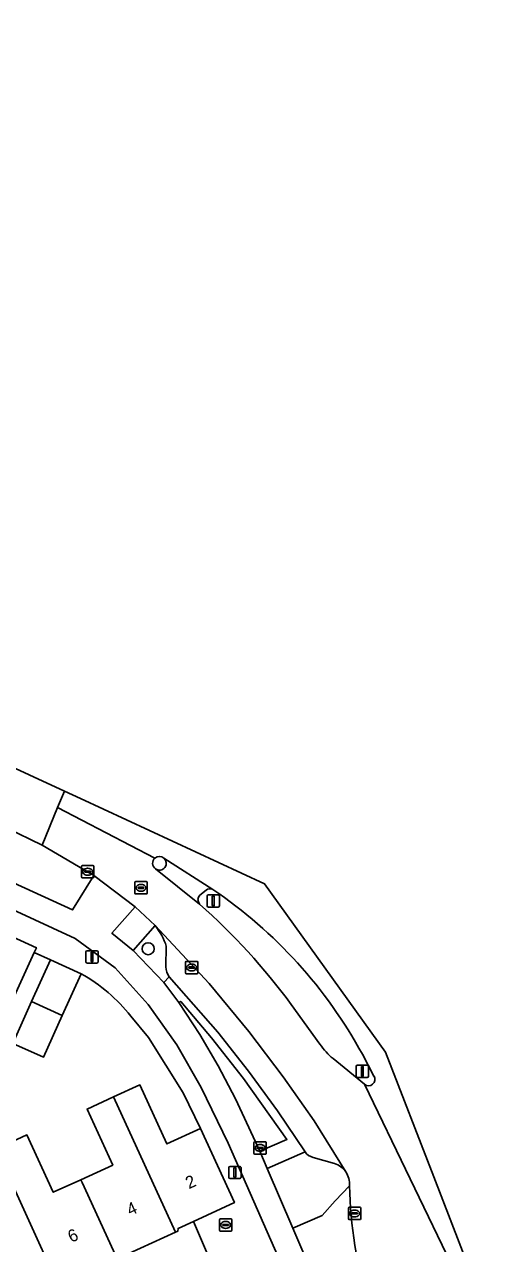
# Model space of a CAD drawing. Extents: x 161838 to 162344, y 381620 to 382160.
# Drawn here: x 162267.7 to 162305.1, y 381756.3 to 381855.3 of the extents above; entities that cross this region are included whole.
import ezdxf

# ---------------------------------------------------------------- set-up
doc = ezdxf.new("R2010")
doc.units = 0
for name, color, linetype in [('IMGEO_Berm_groen', 7, 'Continuous'), ('IMGEO_Boom', 7, 'Continuous'), ('IMGEO_Brandkraan', 7, 'Continuous'), ('IMGEO_Erf', 7, 'Continuous'), ('IMGEO_Kolk', 7, 'Continuous'), ('IMGEO_Lichtmast', 7, 'Continuous'), ('IMGEO_Muur', 7, 'Continuous'), ('IMGEO_Pand', 7, 'Continuous'), ('IMGEO_Pand_nummerreeks', 7, 'Continuous'), ('IMGEO_Parkeervlak_open', 7, 'Continuous'), ('IMGEO_Rijbaan_lokaal_gesloten', 7, 'Continuous'), ('IMGEO_Rioolput', 7, 'Continuous'), ('IMGEO_Verkeerseiland_groen', 7, 'Continuous'), ('IMGEO_Verkeerseiland_open', 7, 'Continuous'), ('IMGEO_Voetpad_gesloten', 7, 'Continuous'), ('IMGEO_Voetpad_open', 7, 'Continuous')]:
    doc.layers.add(name, color=color, linetype=linetype)

msp = doc.modelspace()

# ---------------------------------------------------------------- linework, layer by layer
at = {"layer": 'IMGEO_Berm_groen'}
for points in [[(162278.32, 381782.137), (162276.556, 381780.102), (162279.031, 381777.525), (162279.473, 381777.981)], [(162279.197, 381778.777), (162279.235, 381780.454)], [(162290.497, 381763.771), (162287.421, 381762.394), (162289.504, 381757.563), (162291.89, 381758.597), (162292.955, 381759.774), (162294.11, 381761.009)], [(162292.898, 381762.818), (162291.154, 381763.302)]]:
    msp.add_lwpolyline(points, dxfattribs=at)
msp.add_lwpolyline([(162282.909, 381773.006), (162280.411, 381775.98), (162280.238, 381775.879), (162281.96, 381773.297), (162283.451, 381770.742), (162284.848, 381768.06), (162286.825, 381763.803), (162289.022, 381764.764), (162285.512, 381769.728)], close=True, dxfattribs=at)
for centre, radius, start, end in [((162274.478, 381778.958), 4.986, 17.45711, 39.60627), ((162280.501, 381778.783), 1.304, 180.28188, 217.96443), ((162291.365, 381764.292), 1.012, 210.98439, 257.97326), ((162292.325, 381761.122), 1.79, 34.08019, 71.33847), ((162292.331, 381761.126), 1.783, 356.22586, 34.05836)]:
    msp.add_arc(centre, radius, start, end, dxfattribs=at)
at = {"layer": 'IMGEO_Boom'}
msp.add_circle((162277.76, 381780.26), 0.489, dxfattribs=at)
at = {"layer": 'IMGEO_Brandkraan'}
for p, q in [((162283.553, 381757.394), (162283.553, 381758.246)), ((162283.628, 381758.32), (162284.48, 381758.32)), ((162283.812, 381757.814), (162283.812, 381757.826)), ((162284.25, 381757.777), (162283.852, 381757.777)), ((162283.855, 381757.863), (162284.253, 381757.863)), ((162284.041, 381758.1), (162284.066, 381758.1)), ((162284.296, 381757.826), (162284.296, 381757.814)), ((162284.554, 381758.246), (162284.554, 381757.394)), ((162284.48, 381757.32), (162283.628, 381757.32)), ((162284.064, 381757.54), (162284.039, 381757.54))]:
    msp.add_line(p, q, dxfattribs=at)
for points in [[(162283.553, 381757.394), (162283.553, 381758.246)], [(162283.628, 381758.32), (162284.48, 381758.32)], [(162284.554, 381758.246), (162284.554, 381757.394)], [(162284.48, 381757.32), (162283.628, 381757.32)]]:
    msp.add_lwpolyline(points, dxfattribs=at)
for centre, radius, start, end in [((162283.63, 381758.244), 0.0765, 91.55205, 178.44795), ((162283.63, 381758.244), 0.0765, 91.55205, 178.44795), ((162283.852, 381757.823), 0.0403, 85.87752, 175.75265), ((162283.849, 381757.813), 0.0366, 178.93798, 274.71019), ((162284.253, 381757.82), 0.043, 264.86636, 352.45326), ((162284.257, 381757.825), 0.0386, 1.73085, 96.63898), ((162284.478, 381758.244), 0.0765, 1.55205, 88.44795), ((162284.478, 381758.244), 0.0765, 1.55205, 88.44795), ((162283.63, 381757.396), 0.0765, 181.55205, 268.44795), ((162283.63, 381757.396), 0.0765, 181.55205, 268.44795), ((162284.478, 381757.396), 0.0765, 271.55205, 358.44795), ((162284.478, 381757.396), 0.0765, 271.55205, 358.44795)]:
    msp.add_arc(centre, radius, start, end, dxfattribs=at)
for centre, major_axis, ratio, start_param, end_param in [((162284.04, 381757.82), (-0.387, 0.002), 0.722429, 4.712389, 7.853982), ((162284.065, 381757.82), (-0.39, 0.002), 0.717154, 1.570796, 4.712389)]:
    msp.add_ellipse(centre, major_axis=major_axis, ratio=ratio, start_param=start_param, end_param=end_param, dxfattribs=at)
at = {"layer": 'IMGEO_Erf'}
for points in [[(162272.328, 381778.227), (162270.79, 381774.833), (162269.254, 381771.442), (162266.766, 381772.568), (162268.303, 381775.962), (162269.84, 381779.353), (162268.511, 381779.959), (162266.621, 381775.786)], [(162277.781, 381773.055), (162276.358, 381774.78)], [(162260.558, 381756.131), (162262.824, 381757.166), (162265.353, 381758.321), (162263.22, 381762.989), (162265.401, 381763.985), (162267.923, 381765.137), (162270.053, 381760.473), (162272.292, 381761.495), (162274.881, 381762.678), (162272.802, 381767.23), (162274.96, 381768.215), (162277.096, 381769.191), (162279.286, 381764.396), (162282.012, 381765.641), (162280.601, 381768.553), (162277.781, 381773.055)]]:
    msp.add_lwpolyline(points, dxfattribs=at)
msp.add_arc((162265.362, 381766.004), 14.069, 38.59496, 60.32198, dxfattribs=at)
at = {"layer": 'IMGEO_Kolk'}
for p, q in [((162272.355, 381786.085), (162272.355, 381786.937)), ((162272.43, 381787.011), (162273.282, 381787.011)), ((162272.614, 381786.505), (162272.614, 381786.517)), ((162273.052, 381786.468), (162272.654, 381786.468)), ((162272.657, 381786.554), (162273.055, 381786.554)), ((162272.843, 381786.791), (162272.868, 381786.791)), ((162273.098, 381786.517), (162273.098, 381786.505)), ((162273.356, 381786.937), (162273.356, 381786.085)), ((162273.282, 381786.011), (162272.43, 381786.011)), ((162272.866, 381786.231), (162272.841, 381786.231)), ((162280.79, 381778.304), (162280.79, 381779.156)), ((162280.865, 381779.23), (162281.717, 381779.23)), ((162281.049, 381778.724), (162281.049, 381778.736)), ((162281.487, 381778.687), (162281.089, 381778.687)), ((162281.092, 381778.773), (162281.49, 381778.773)), ((162281.301, 381778.45), (162281.276, 381778.45)), ((162281.278, 381779.01), (162281.303, 381779.01)), ((162281.533, 381778.736), (162281.533, 381778.724)), ((162281.791, 381779.156), (162281.791, 381778.304)), ((162281.717, 381778.23), (162280.865, 381778.23)), ((162286.351, 381763.646), (162286.351, 381764.498)), ((162286.426, 381764.572), (162287.278, 381764.572)), ((162287.352, 381764.498), (162287.352, 381763.646)), ((162287.278, 381763.572), (162286.426, 381763.572)), ((162286.61, 381764.066), (162286.61, 381764.078)), ((162287.048, 381764.029), (162286.65, 381764.029)), ((162286.653, 381764.115), (162287.051, 381764.115)), ((162286.862, 381763.792), (162286.837, 381763.792)), ((162286.839, 381764.352), (162286.864, 381764.352)), ((162287.094, 381764.078), (162287.094, 381764.066))]:
    msp.add_line(p, q, dxfattribs=at)
for points in [[(162272.355, 381786.085), (162272.355, 381786.937)], [(162272.43, 381787.011), (162273.282, 381787.011)], [(162273.356, 381786.937), (162273.356, 381786.085)], [(162273.282, 381786.011), (162272.43, 381786.011)], [(162280.79, 381778.304), (162280.79, 381779.156)], [(162280.865, 381779.23), (162281.717, 381779.23)], [(162281.791, 381779.156), (162281.791, 381778.304)], [(162281.717, 381778.23), (162280.865, 381778.23)], [(162286.351, 381763.646), (162286.351, 381764.498)], [(162286.426, 381764.572), (162287.278, 381764.572)], [(162287.352, 381764.498), (162287.352, 381763.646)], [(162287.278, 381763.572), (162286.426, 381763.572)]]:
    msp.add_lwpolyline(points, dxfattribs=at)
for centre, radius, start, end in [((162272.432, 381786.935), 0.0765, 91.55205, 178.44795), ((162272.432, 381786.935), 0.0765, 91.55205, 178.44795), ((162272.654, 381786.514), 0.0403, 85.87752, 175.75265), ((162272.651, 381786.504), 0.0366, 178.93798, 274.71019), ((162273.055, 381786.511), 0.043, 264.86636, 352.45326), ((162273.059, 381786.516), 0.0386, 1.73085, 96.63898), ((162273.28, 381786.935), 0.0765, 1.55205, 88.44795), ((162273.28, 381786.935), 0.0765, 1.55205, 88.44795), ((162272.432, 381786.087), 0.0765, 181.55205, 268.44795), ((162272.432, 381786.087), 0.0765, 181.55205, 268.44795), ((162273.28, 381786.087), 0.0765, 271.55205, 358.44795), ((162273.28, 381786.087), 0.0765, 271.55205, 358.44795), ((162280.867, 381779.154), 0.0765, 91.55205, 178.44795), ((162280.867, 381779.154), 0.0765, 91.55205, 178.44795), ((162281.089, 381778.733), 0.0403, 85.87752, 175.75265), ((162281.086, 381778.723), 0.0366, 178.93798, 274.71019), ((162281.49, 381778.73), 0.043, 264.86636, 352.45326), ((162281.494, 381778.735), 0.0386, 1.73085, 96.63898), ((162281.715, 381779.154), 0.0765, 1.55205, 88.44795), ((162281.715, 381779.154), 0.0765, 1.55205, 88.44795), ((162280.867, 381778.306), 0.0765, 181.55205, 268.44795), ((162280.867, 381778.306), 0.0765, 181.55205, 268.44795), ((162281.715, 381778.306), 0.0765, 271.55205, 358.44795), ((162281.715, 381778.306), 0.0765, 271.55205, 358.44795), ((162286.428, 381764.496), 0.0765, 91.55205, 178.44795), ((162286.428, 381764.496), 0.0765, 91.55205, 178.44795), ((162287.276, 381764.496), 0.0765, 1.55205, 88.44795), ((162287.276, 381764.496), 0.0765, 1.55205, 88.44795), ((162286.428, 381763.648), 0.0765, 181.55205, 268.44795), ((162286.428, 381763.648), 0.0765, 181.55205, 268.44795), ((162286.65, 381764.075), 0.0403, 85.87752, 175.75265), ((162286.647, 381764.065), 0.0366, 178.93798, 274.71019), ((162287.051, 381764.072), 0.043, 264.86636, 352.45326), ((162287.055, 381764.077), 0.0386, 1.73085, 96.63898), ((162287.276, 381763.648), 0.0765, 271.55205, 358.44795), ((162287.276, 381763.648), 0.0765, 271.55205, 358.44795)]:
    msp.add_arc(centre, radius, start, end, dxfattribs=at)
for centre, major_axis, ratio, start_param, end_param in [((162272.842, 381786.511), (-0.387, 0.002), 0.722429, 4.712389, 7.853982), ((162272.867, 381786.511), (-0.39, 0.002), 0.717154, 1.570796, 4.712389), ((162281.277, 381778.73), (-0.387, 0.002), 0.722429, 4.712389, 7.853982), ((162281.302, 381778.73), (-0.39, 0.002), 0.717154, 1.570796, 4.712389), ((162286.838, 381764.072), (-0.387, 0.002), 0.722429, 4.712389, 7.853982), ((162286.863, 381764.072), (-0.39, 0.002), 0.717154, 1.570796, 4.712389)]:
    msp.add_ellipse(centre, major_axis=major_axis, ratio=ratio, start_param=start_param, end_param=end_param, dxfattribs=at)
at = {"layer": 'IMGEO_Lichtmast'}
for p, q in [((162282.551, 381783.74), (162282.551, 381784.54)), ((162282.551, 381784.54), (162282.551, 381783.74)), ((162282.651, 381784.64), (162283.441, 381784.64)), ((162283.441, 381784.64), (162282.651, 381784.64)), ((162283.541, 381784.54), (162283.541, 381783.74)), ((162283.541, 381783.74), (162283.541, 381784.54)), ((162283.441, 381783.64), (162282.651, 381783.64)), ((162282.651, 381783.64), (162283.441, 381783.64)), ((162272.706, 381779.197), (162272.706, 381779.997)), ((162272.706, 381779.997), (162272.706, 381779.197)), ((162272.806, 381780.097), (162273.596, 381780.097)), ((162273.596, 381780.097), (162272.806, 381780.097)), ((162273.696, 381779.997), (162273.696, 381779.197)), ((162273.696, 381779.197), (162273.696, 381779.997)), ((162273.596, 381779.097), (162272.806, 381779.097)), ((162272.806, 381779.097), (162273.596, 381779.097)), ((162294.657, 381769.903), (162294.657, 381770.703)), ((162294.657, 381770.703), (162294.657, 381769.903)), ((162294.757, 381770.803), (162295.547, 381770.803)), ((162295.547, 381770.803), (162294.757, 381770.803)), ((162295.647, 381770.703), (162295.647, 381769.903)), ((162295.647, 381769.903), (162295.647, 381770.703)), ((162295.547, 381769.803), (162294.757, 381769.803)), ((162294.757, 381769.803), (162295.547, 381769.803)), ((162284.409, 381762.58), (162285.199, 381762.58)), ((162285.199, 381762.58), (162284.409, 381762.58)), ((162284.309, 381761.68), (162284.309, 381762.48)), ((162284.309, 381762.48), (162284.309, 381761.68)), ((162285.199, 381761.58), (162284.409, 381761.58)), ((162284.409, 381761.58), (162285.199, 381761.58)), ((162285.299, 381762.48), (162285.299, 381761.68)), ((162285.299, 381761.68), (162285.299, 381762.48))]:
    msp.add_line(p, q, dxfattribs=at)
for points in [[(162282.971, 381784.515), (162283.121, 381784.515), (162283.121, 381783.765), (162282.971, 381783.765), (162282.971, 381784.515)], [(162273.126, 381779.972), (162273.276, 381779.972), (162273.276, 381779.222), (162273.126, 381779.222), (162273.126, 381779.972)], [(162295.077, 381770.678), (162295.227, 381770.678), (162295.227, 381769.928), (162295.077, 381769.928), (162295.077, 381770.678)], [(162284.729, 381762.455), (162284.879, 381762.455), (162284.879, 381761.705), (162284.729, 381761.705), (162284.729, 381762.455)]]:
    msp.add_lwpolyline(points, dxfattribs=at)
for centre, start, end in [((162282.651, 381784.54), 90, 180), ((162282.651, 381784.54), 90, 180), ((162283.441, 381784.54), 0, 90), ((162283.441, 381784.54), 360, 90), ((162282.651, 381783.74), 180, 270), ((162282.651, 381783.74), 180, 270), ((162283.441, 381783.74), 270, 0), ((162283.441, 381783.74), 270, 0), ((162272.806, 381779.997), 90, 180), ((162272.806, 381779.997), 90, 180), ((162273.596, 381779.997), 0, 90), ((162273.596, 381779.997), 360, 90), ((162272.806, 381779.197), 180, 270), ((162272.806, 381779.197), 180, 270), ((162273.596, 381779.197), 270, 0), ((162273.596, 381779.197), 270, 0), ((162294.757, 381770.703), 90, 180), ((162294.757, 381770.703), 90, 180), ((162295.547, 381770.703), 0, 90), ((162295.547, 381770.703), 360, 90), ((162294.757, 381769.903), 180, 270), ((162294.757, 381769.903), 180, 270), ((162295.547, 381769.903), 270, 0), ((162295.547, 381769.903), 270, 0), ((162284.409, 381762.48), 90, 180), ((162284.409, 381762.48), 90, 180), ((162285.199, 381762.48), 0, 90), ((162285.199, 381762.48), 360, 90), ((162284.409, 381761.68), 180, 270), ((162284.409, 381761.68), 180, 270), ((162285.199, 381761.68), 270, 0), ((162285.199, 381761.68), 270, 0)]:
    msp.add_arc(centre, 0.1, start, end, dxfattribs=at)
at = {"layer": 'IMGEO_Muur'}
msp.add_lwpolyline([(162282.012, 381765.641), (162280.601, 381768.553), (162277.781, 381773.055), (162276.358, 381774.78)], dxfattribs=at)
msp.add_arc((162265.362, 381766.004), 14.069, 38.59496, 60.32198, dxfattribs=at)
at = {"layer": 'IMGEO_Pand'}
for points in [[(162268.511, 381779.959), (162268.684, 381780.34), (162263.818, 381782.544), (162259.038, 381771.993), (162258.797, 381771.462), (162260.937, 381770.522), (162261.213, 381770.397), (162263.421, 381775.27), (162265.882, 381774.155), (162266.621, 381775.786)], [(162270.79, 381774.833), (162272.328, 381778.227), (162269.84, 381779.353), (162268.303, 381775.962)], [(162270.79, 381774.833), (162268.303, 381775.962), (162266.766, 381772.568), (162269.254, 381771.442)], [(162282.012, 381765.641), (162279.286, 381764.396), (162277.096, 381769.191), (162274.96, 381768.215), (162279.982, 381757.228), (162280.166, 381757.312), (162280.189, 381757.543), (162281.432, 381758.111), (162284.758, 381759.63)], [(162279.982, 381757.228), (162274.96, 381768.215), (162272.802, 381767.23), (162274.881, 381762.678), (162272.292, 381761.495), (162272.402, 381761.254), (162275.235, 381755.059)], [(162265.401, 381763.985), (162265.461, 381763.881), (162270.411, 381753.052), (162275.087, 381755.22), (162275.064, 381754.981), (162275.235, 381755.059), (162272.402, 381761.254), (162272.292, 381761.495), (162270.053, 381760.473), (162267.923, 381765.137)], [(162265.461, 381763.881), (162265.401, 381763.985), (162263.22, 381762.989), (162265.353, 381758.321), (162262.824, 381757.166), (162265.676, 381750.857), (162270.411, 381753.052)]]:
    msp.add_lwpolyline(points, close=True, dxfattribs=at)
at = {"layer": 'IMGEO_Parkeervlak_open'}
for points in [[(162293.808, 381762.125), (162291.248, 381766.267), (162288.729, 381769.86), (162285.929, 381773.537), (162282.721, 381777.43), (162278.32, 381782.137)], [(162279.235, 381780.454), (162279.197, 381778.777)], [(162279.473, 381777.981), (162283.411, 381773.471), (162285.912, 381770.323), (162288.266, 381767.079), (162290.497, 381763.771)], [(162291.154, 381763.302), (162292.898, 381762.818)]]:
    msp.add_lwpolyline(points, dxfattribs=at)
for centre, radius, start, end in [((162274.478, 381778.958), 4.986, 17.45711, 39.60627), ((162280.501, 381778.783), 1.304, 180.28188, 217.96443), ((162291.365, 381764.292), 1.012, 210.98439, 257.97326), ((162292.325, 381761.122), 1.79, 34.08019, 71.33847)]:
    msp.add_arc(centre, radius, start, end, dxfattribs=at)
at = {"layer": 'IMGEO_Rijbaan_lokaal_gesloten'}
for points in [[(162174.607, 381831.399), (162189.905, 381824.561), (162190.345, 381824.364), (162197.539, 381821.152), (162203.924, 381818.301), (162204.044, 381818.258), (162266.265, 381790.084), (162269.159, 381788.667), (162270.414, 381791.728), (162270.956, 381793.049), (162163.289, 381842.84), (162157.474, 381846.239)], [(162305.075, 381751.053), (162300.951, 381761.738), (162297.043, 381771.864), (162287.214, 381785.531), (162272.258, 381792.447), (162270.956, 381793.049), (162270.414, 381791.728), (162278.312, 381787.616)], [(162278.312, 381787.616), (162270.414, 381791.728), (162269.159, 381788.667), (162273.356, 381786.194), (162276.701, 381783.665), (162278.32, 381782.137), (162282.721, 381777.43), (162285.929, 381773.537), (162288.729, 381769.86), (162291.248, 381766.267), (162293.808, 381762.125)], [(162279.038, 381787.612), (162283.019, 381785.067)], [(162281.936, 381783.879), (162278.362, 381786.75)], [(162291.706, 381772.503), (162289.369, 381775.736)], [(162295.151, 381771.682), (162296.096, 381769.905)], [(162302.75, 381753.874), (162295.318, 381769.244), (162292.781, 381771.328)], [(162295.318, 381769.244), (162302.75, 381753.874), (162303.888, 381752.705)]]:
    msp.add_lwpolyline(points, dxfattribs=at)
for centre, radius, start, end in [((162278.673, 381787.202), 0.549, 131.0849, 235.5239), ((162278.673, 381787.202), 0.549, 48.32987, 131.03878), ((162261.572, 381753.437), 38.215, 28.51695, 55.8606), ((162247.28, 381744.78), 52.247, 36.33348, 48.44671), ((162296.355, 381775.677), 5.629, 214.32265, 230.58774), ((162295.648, 381769.644), 0.519, 230.47063, 30.23278), ((162292.331, 381761.126), 1.783, 356.22586, 34.05836), ((162326.441, 381761.439), 32.333, 180.76204, 198.03065)]:
    msp.add_arc(centre, radius, start, end, dxfattribs=at)
at = {"layer": 'IMGEO_Rioolput'}
for p, q in [((162276.681, 381784.779), (162276.681, 381785.631)), ((162276.756, 381785.705), (162277.608, 381785.705)), ((162277.169, 381785.485), (162277.194, 381785.485)), ((162277.682, 381785.631), (162277.682, 381784.779)), ((162277.608, 381784.705), (162276.756, 381784.705)), ((162276.94, 381785.199), (162276.94, 381785.211)), ((162277.378, 381785.162), (162276.98, 381785.162)), ((162276.983, 381785.248), (162277.381, 381785.248)), ((162277.192, 381784.925), (162277.167, 381784.925)), ((162277.424, 381785.211), (162277.424, 381785.199)), ((162294.019, 381758.327), (162294.019, 381759.179)), ((162294.094, 381759.253), (162294.946, 381759.253)), ((162294.278, 381758.747), (162294.278, 381758.759)), ((162294.716, 381758.71), (162294.318, 381758.71)), ((162294.321, 381758.796), (162294.719, 381758.796)), ((162294.507, 381759.033), (162294.532, 381759.033)), ((162294.762, 381758.759), (162294.762, 381758.747)), ((162295.02, 381759.179), (162295.02, 381758.327)), ((162294.946, 381758.253), (162294.094, 381758.253)), ((162294.53, 381758.473), (162294.505, 381758.473))]:
    msp.add_line(p, q, dxfattribs=at)
for points in [[(162276.681, 381784.779), (162276.681, 381785.631)], [(162276.756, 381785.705), (162277.608, 381785.705)], [(162277.682, 381785.631), (162277.682, 381784.779)], [(162277.608, 381784.705), (162276.756, 381784.705)], [(162294.019, 381758.327), (162294.019, 381759.179)], [(162294.094, 381759.253), (162294.946, 381759.253)], [(162295.02, 381759.179), (162295.02, 381758.327)], [(162294.946, 381758.253), (162294.094, 381758.253)]]:
    msp.add_lwpolyline(points, dxfattribs=at)
for centre, radius, start, end in [((162276.758, 381785.629), 0.0765, 91.55205, 178.44795), ((162276.758, 381785.629), 0.0765, 91.55205, 178.44795), ((162277.606, 381785.629), 0.0765, 1.55205, 88.44795), ((162277.606, 381785.629), 0.0765, 1.55205, 88.44795), ((162276.758, 381784.781), 0.0765, 181.55205, 268.44795), ((162276.758, 381784.781), 0.0765, 181.55205, 268.44795), ((162276.98, 381785.208), 0.0403, 85.87752, 175.75265), ((162276.977, 381785.198), 0.0366, 178.93798, 274.71019), ((162277.381, 381785.205), 0.043, 264.86636, 352.45326), ((162277.385, 381785.21), 0.0386, 1.73085, 96.63898), ((162277.606, 381784.781), 0.0765, 271.55205, 358.44795), ((162277.606, 381784.781), 0.0765, 271.55205, 358.44795), ((162294.096, 381759.177), 0.0765, 91.55205, 178.44795), ((162294.096, 381759.177), 0.0765, 91.55205, 178.44795), ((162294.318, 381758.756), 0.0403, 85.87752, 175.75265), ((162294.315, 381758.746), 0.0366, 178.93798, 274.71019), ((162294.719, 381758.753), 0.043, 264.86636, 352.45326), ((162294.723, 381758.758), 0.0386, 1.73085, 96.63898), ((162294.944, 381759.177), 0.0765, 1.55205, 88.44795), ((162294.944, 381759.177), 0.0765, 1.55205, 88.44795), ((162294.096, 381758.329), 0.0765, 181.55205, 268.44795), ((162294.096, 381758.329), 0.0765, 181.55205, 268.44795), ((162294.944, 381758.329), 0.0765, 271.55205, 358.44795), ((162294.944, 381758.329), 0.0765, 271.55205, 358.44795)]:
    msp.add_arc(centre, radius, start, end, dxfattribs=at)
for centre, major_axis, ratio, start_param, end_param in [((162277.168, 381785.205), (-0.387, 0.002), 0.722429, 4.712389, 7.853982), ((162277.193, 381785.205), (-0.39, 0.002), 0.717154, 1.570796, 4.712389), ((162294.506, 381758.753), (-0.387, 0.002), 0.722429, 4.712389, 7.853982), ((162294.531, 381758.753), (-0.39, 0.002), 0.717154, 1.570796, 4.712389)]:
    msp.add_ellipse(centre, major_axis=major_axis, ratio=ratio, start_param=start_param, end_param=end_param, dxfattribs=at)
at = {"layer": 'IMGEO_Verkeerseiland_groen'}
for points in [[(162262.797, 381789.506), (162262.003, 381787.815), (162271.63, 381783.405), (162273.356, 381786.194), (162269.159, 381788.667)], [(162269.159, 381788.667), (162266.265, 381790.084)]]:
    msp.add_lwpolyline(points, dxfattribs=at)
at = {"layer": 'IMGEO_Verkeerseiland_open'}
for points in [[(162283.019, 381785.067), (162279.038, 381787.612)], [(162278.362, 381786.75), (162281.936, 381783.879)], [(162282.465, 381785.01), (162281.957, 381784.618)], [(162281.957, 381784.618), (162282.465, 381785.01)], [(162289.369, 381775.736), (162291.706, 381772.503)], [(162296.096, 381769.905), (162295.151, 381771.682)], [(162292.781, 381771.328), (162295.318, 381769.244)]]:
    msp.add_lwpolyline(points, dxfattribs=at)
for centre, radius, start, end in [((162278.673, 381787.202), 0.549, 131.0849, 235.5239), ((162278.673, 381787.202), 0.549, 48.32987, 131.03878), ((162278.686, 381787.192), 0.548, 233.75563, 50.03568), ((162278.686, 381787.192), 0.548, 233.75563, 50.03568), ((162282.362, 381784.237), 0.556, 136.73034, 220.01421), ((162282.362, 381784.237), 0.556, 136.73034, 220.01421), ((162282.785, 381784.621), 0.504, 62.3083, 129.44047), ((162282.785, 381784.621), 0.504, 62.3083, 129.44047), ((162261.572, 381753.437), 38.215, 28.51695, 55.8606), ((162247.28, 381744.78), 52.247, 36.33348, 48.44671), ((162296.355, 381775.677), 5.629, 214.32265, 230.58774), ((162295.648, 381769.644), 0.519, 230.47063, 30.23278)]:
    msp.add_arc(centre, radius, start, end, dxfattribs=at)
at = {"layer": 'IMGEO_Voetpad_gesloten'}
for points in [[(162125.545, 381859.011), (162130.429, 381854.037), (162134.882, 381849.978), (162140.263, 381845.513), (162147.552, 381840.181), (162154.18, 381835.7), (162160.086, 381831.935), (162165.238, 381828.801), (162168.761, 381826.912), (162197.313, 381814.891), (162266.754, 381783.434), (162271.828, 381781.089), (162275.072, 381778.709), (162277.759, 381775.733), (162280.091, 381772.447), (162282.076, 381768.974), (162284.268, 381764.473), (162289.497, 381752.523), (162295.191, 381737.537), (162297.128, 381732.914), (162299.208, 381728.355), (162301.472, 381723.885)], [(162291.289, 381753.398), (162289.504, 381757.563), (162287.421, 381762.394), (162286.825, 381763.803), (162284.848, 381768.06), (162283.451, 381770.742), (162281.96, 381773.297), (162280.238, 381775.879), (162279.031, 381777.525), (162276.556, 381780.102), (162274.816, 381781.511), (162276.701, 381783.665), (162273.356, 381786.194), (162271.63, 381783.405), (162262.003, 381787.815)]]:
    msp.add_lwpolyline(points, dxfattribs=at)
at = {"layer": 'IMGEO_Voetpad_open'}
for points in [[(162276.358, 381774.78), (162277.781, 381773.055), (162280.601, 381768.553), (162282.012, 381765.641), (162284.758, 381759.63), (162281.432, 381758.111), (162282.997, 381754.511), (162284.936, 381750.434), (162289.497, 381752.523), (162284.268, 381764.473), (162282.076, 381768.974), (162280.091, 381772.447), (162277.759, 381775.733), (162275.072, 381778.709), (162271.828, 381781.089), (162266.754, 381783.434), (162197.313, 381814.891), (162168.761, 381826.912)], [(162199.091, 381811.761), (162206.304, 381808.493), (162212.652, 381805.617), (162219.499, 381802.515), (162226.946, 381799.168), (162248.332, 381789.557), (162249.437, 381789.06), (162254.302, 381786.856), (162259.06, 381784.7), (162263.818, 381782.544), (162268.684, 381780.34), (162268.511, 381779.959), (162269.84, 381779.353), (162272.328, 381778.227)], [(162294.11, 381761.009), (162292.955, 381759.774), (162291.89, 381758.597), (162289.504, 381757.563), (162291.289, 381753.398), (162293.643, 381747.456), (162294.53, 381747.813), (162296.479, 381743.618), (162297.084, 381743.867), (162295.356, 381747.694), (162295.14, 381748.145), (162295.76, 381748.502)], [(162282.997, 381754.511), (162281.432, 381758.111), (162280.189, 381757.543), (162280.166, 381757.312), (162279.982, 381757.228), (162275.235, 381755.059)]]:
    msp.add_lwpolyline(points, dxfattribs=at)
for points in [[(162276.701, 381783.665), (162274.816, 381781.511), (162276.556, 381780.102), (162278.32, 381782.137)], [(162287.421, 381762.394), (162290.497, 381763.771), (162288.266, 381767.079), (162285.912, 381770.323), (162283.411, 381773.471), (162279.473, 381777.981), (162279.031, 381777.525), (162280.238, 381775.879), (162280.411, 381775.98), (162282.909, 381773.006), (162285.512, 381769.728), (162289.022, 381764.764), (162286.825, 381763.803)]]:
    msp.add_lwpolyline(points, close=True, dxfattribs=at)
for centre, radius, start, end in [((162265.362, 381766.004), 14.069, 38.59496, 60.32198), ((162326.441, 381761.439), 32.333, 180.76204, 198.03065)]:
    msp.add_arc(centre, radius, start, end, dxfattribs=at)

# ---------------------------------------------------------------- texts
at = {"layer": 'IMGEO_Pand_nummerreeks'}
for s, rotation, p in [('2', 24.53405, (162281.071, 381760.717)), ('4', 24.53144, (162276.296, 381758.538)), ('6', 24.53144, (162271.519, 381756.358))]:
    msp.add_text(s, height=1, rotation=rotation, dxfattribs=at).set_placement(p)

doc.saveas('drawing.dxf')
